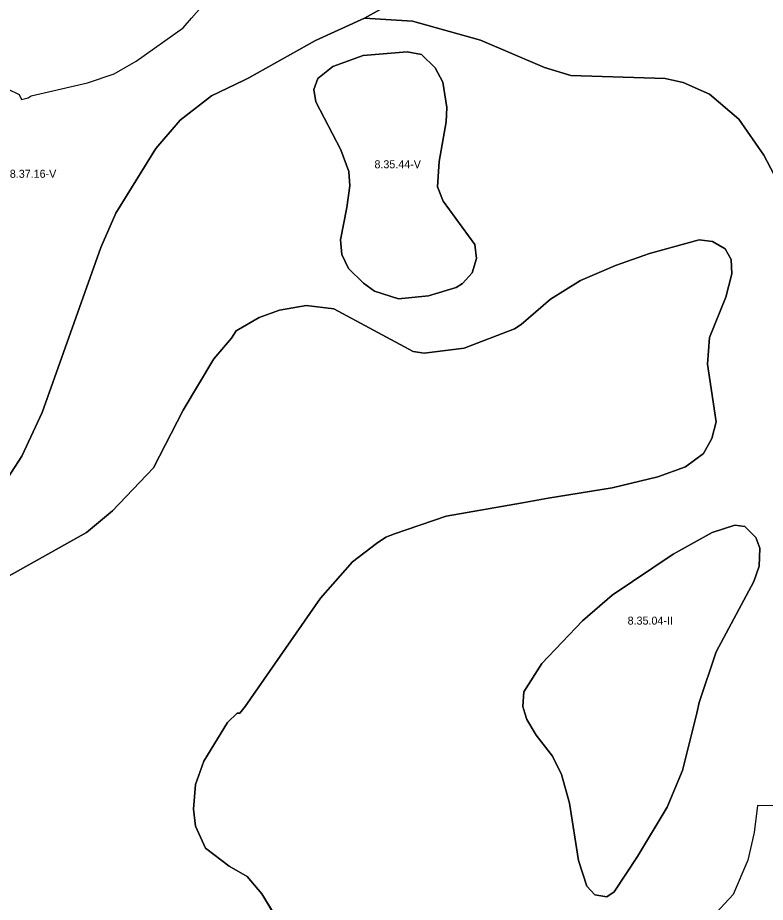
# Model space of a CAD drawing. Extents: x -547623 to -533936, y -1096714 to -1086523.
# Drawn here: x -542784 to -541850, y -1093236 to -1092131 of the extents above; entities that cross this region are included whole.
import ezdxf

# ---------------------------------------------------------------- set-up
doc = ezdxf.new("R2010")
doc.units = 0
for name, color, linetype in [('Vrstva 27', 7, 'Continuous'), ('Vrstva 28', 7, 'Continuous'), ('Vrstva 29', 7, 'Continuous')]:
    doc.layers.add(name, color=color, linetype=linetype)

msp = doc.modelspace()

# ---------------------------------------------------------------- linework, layer by layer
at = {"layer": 'Vrstva 28'}
for p, q in [((-542351, -1092132), (-542270.5, -1092087.5)), ((-542270.5, -1092087.5), (-542351, -1092132)), ((-542412, -1092160), (-542351, -1092132)), ((-542351, -1092132), (-542412, -1092160)), ((-542291, -1092136), (-542351, -1092132)), ((-542351, -1092132), (-542291, -1092136)), ((-542206, -1092159.5), (-542291, -1092136)), ((-542291, -1092136), (-542206, -1092159.5)), ((-542495.5, -1092206.5), (-542412, -1092160)), ((-542412, -1092160), (-542495.5, -1092206.5)), ((-542126, -1092193.5), (-542206, -1092159.5)), ((-542206, -1092159.5), (-542126, -1092193.5)), ((-542297.5, -1092174), (-542352.5, -1092178.5)), ((-542352.5, -1092178.5), (-542297.5, -1092174)), ((-542279.5, -1092177.5), (-542297.5, -1092174)), ((-542297.5, -1092174), (-542279.5, -1092177.5)), ((-542352.5, -1092178.5), (-542390.5, -1092192.5)), ((-542390.5, -1092192.5), (-542352.5, -1092178.5)), ((-542262.5, -1092194), (-542279.5, -1092177.5)), ((-542279.5, -1092177.5), (-542262.5, -1092194)), ((-542390.5, -1092192.5), (-542409, -1092207.5)), ((-542409, -1092207.5), (-542390.5, -1092192.5)), ((-542253, -1092212), (-542262.5, -1092194)), ((-542262.5, -1092194), (-542253, -1092212)), ((-542093, -1092203.5), (-542126, -1092193.5)), ((-542126, -1092193.5), (-542093, -1092203.5)), ((-542502, -1092210), (-542495.5, -1092206.5)), ((-542495.5, -1092206.5), (-542502, -1092210)), ((-542409, -1092207.5), (-542414, -1092221)), ((-542414, -1092221), (-542409, -1092207.5)), ((-541975.5, -1092207.5), (-542093, -1092203.5)), ((-542093, -1092203.5), (-541975.5, -1092207.5)), ((-541953, -1092212.5), (-541975.5, -1092207.5)), ((-541975.5, -1092207.5), (-541953, -1092212.5)), ((-542542, -1092229), (-542502, -1092210)), ((-542502, -1092210), (-542542, -1092229)), ((-542248, -1092243.5), (-542253, -1092212)), ((-542253, -1092212), (-542248, -1092243.5)), ((-541920, -1092227), (-541953, -1092212.5)), ((-541953, -1092212.5), (-541920, -1092227)), ((-542581, -1092259.5), (-542542, -1092229)), ((-542542, -1092229), (-542581, -1092259.5)), ((-542414, -1092221), (-542411.5, -1092236.5)), ((-542411.5, -1092236.5), (-542414, -1092221)), ((-541883.5, -1092258), (-541920, -1092227)), ((-541920, -1092227), (-541883.5, -1092258)), ((-542411.5, -1092236.5), (-542380.5, -1092296.5)), ((-542380.5, -1092296.5), (-542411.5, -1092236.5)), ((-542249, -1092261.5), (-542248, -1092243.5)), ((-542248, -1092243.5), (-542249, -1092261.5)), ((-542611.5, -1092295), (-542581, -1092259.5)), ((-542581, -1092259.5), (-542611.5, -1092295)), ((-542257.5, -1092311), (-542249, -1092261.5)), ((-542249, -1092261.5), (-542257.5, -1092311)), ((-541852, -1092303), (-541883.5, -1092258)), ((-541883.5, -1092258), (-541852, -1092303)), ((-542661.5, -1092375.5), (-542611.5, -1092295)), ((-542611.5, -1092295), (-542661.5, -1092375.5)), ((-542380.5, -1092296.5), (-542370.5, -1092323.5)), ((-542370.5, -1092323.5), (-542380.5, -1092296.5)), ((-541830.5, -1092344.5), (-541852, -1092303)), ((-541852, -1092303), (-541830.5, -1092344.5)), ((-542259.5, -1092342.5), (-542257.5, -1092311)), ((-542257.5, -1092311), (-542259.5, -1092342.5)), ((-542370.5, -1092323.5), (-542369, -1092341.5)), ((-542369, -1092341.5), (-542370.5, -1092323.5)), ((-542369, -1092341.5), (-542373, -1092368.5)), ((-542373, -1092368.5), (-542369, -1092341.5)), ((-542252.5, -1092360.5), (-542259.5, -1092342.5)), ((-542259.5, -1092342.5), (-542252.5, -1092360.5)), ((-542213, -1092414.5), (-542252.5, -1092360.5)), ((-542252.5, -1092360.5), (-542213, -1092414.5)), ((-542373, -1092368.5), (-542381, -1092409)), ((-542381, -1092409), (-542373, -1092368.5)), ((-542680, -1092418.5), (-542661.5, -1092375.5)), ((-542661.5, -1092375.5), (-542680, -1092418.5)), ((-542381, -1092409), (-542379, -1092427)), ((-542379, -1092427), (-542381, -1092409)), ((-542211, -1092432), (-542213, -1092414.5)), ((-542213, -1092414.5), (-542211, -1092432)), ((-541995, -1092426), (-541933, -1092409)), ((-541933, -1092409), (-541995, -1092426)), ((-541933, -1092409), (-541916, -1092411)), ((-541916, -1092411), (-541933, -1092409)), ((-541916, -1092411), (-541900.5, -1092420)), ((-541900.5, -1092420), (-541916, -1092411)), ((-542753.5, -1092624.5), (-542680, -1092418.5)), ((-542680, -1092418.5), (-542753.5, -1092624.5)), ((-542379, -1092427), (-542371, -1092444.5)), ((-542371, -1092444.5), (-542379, -1092427)), ((-542037.5, -1092441), (-541995, -1092426)), ((-541995, -1092426), (-542037.5, -1092441)), ((-541900.5, -1092420), (-541893, -1092433.5)), ((-541893, -1092433.5), (-541900.5, -1092420)), ((-542216.5, -1092450), (-542211, -1092432)), ((-542211, -1092432), (-542216.5, -1092450)), ((-541893, -1092433.5), (-541892, -1092451.5)), ((-541892, -1092451.5), (-541893, -1092433.5)), ((-542371, -1092444.5), (-542352, -1092463)), ((-542352, -1092463), (-542371, -1092444.5)), ((-542228.5, -1092463.5), (-542216.5, -1092450)), ((-542216.5, -1092450), (-542228.5, -1092463.5)), ((-542081, -1092459.5), (-542037.5, -1092441)), ((-542037.5, -1092441), (-542081, -1092459.5)), ((-542118.5, -1092483), (-542081, -1092459.5)), ((-542081, -1092459.5), (-542118.5, -1092483)), ((-541892, -1092451.5), (-541899.5, -1092480.5)), ((-541899.5, -1092480.5), (-541892, -1092451.5)), ((-542352, -1092463), (-542338.5, -1092473)), ((-542338.5, -1092473), (-542352, -1092463)), ((-542338.5, -1092473), (-542308.5, -1092482.5)), ((-542308.5, -1092482.5), (-542338.5, -1092473)), ((-542271, -1092479), (-542236.5, -1092468.5)), ((-542236.5, -1092468.5), (-542271, -1092479)), ((-542236.5, -1092468.5), (-542228.5, -1092463.5)), ((-542228.5, -1092463.5), (-542236.5, -1092468.5)), ((-542308.5, -1092482.5), (-542271, -1092479)), ((-542271, -1092479), (-542308.5, -1092482.5)), ((-542155, -1092514.5), (-542118.5, -1092483)), ((-542118.5, -1092483), (-542155, -1092514.5)), ((-541899.5, -1092480.5), (-541920, -1092531)), ((-541920, -1092531), (-541899.5, -1092480.5)), ((-542457, -1092496.5), (-542423.5, -1092491)), ((-542423.5, -1092491), (-542457, -1092496.5)), ((-542423.5, -1092491), (-542389, -1092495)), ((-542389, -1092495), (-542423.5, -1092491)), ((-542389, -1092495), (-542290, -1092548.5)), ((-542290, -1092548.5), (-542389, -1092495)), ((-542511, -1092522.5), (-542482.5, -1092506)), ((-542482.5, -1092506), (-542511, -1092522.5)), ((-542482.5, -1092506), (-542457, -1092496.5)), ((-542457, -1092496.5), (-542482.5, -1092506)), ((-542163.5, -1092520), (-542155, -1092514.5)), ((-542155, -1092514.5), (-542163.5, -1092520)), ((-542517, -1092531.5), (-542511, -1092522.5)), ((-542511, -1092522.5), (-542517, -1092531.5)), ((-542226.5, -1092544), (-542163.5, -1092520)), ((-542163.5, -1092520), (-542226.5, -1092544)), ((-542539, -1092557.5), (-542517, -1092531.5)), ((-542517, -1092531.5), (-542539, -1092557.5)), ((-541920, -1092531), (-541922.5, -1092564)), ((-541922.5, -1092564), (-541920, -1092531)), ((-542290, -1092548.5), (-542276.5, -1092550.5)), ((-542276.5, -1092550.5), (-542290, -1092548.5)), ((-542276.5, -1092550.5), (-542226.5, -1092544)), ((-542226.5, -1092544), (-542276.5, -1092550.5)), ((-542577.5, -1092621.5), (-542539, -1092557.5)), ((-542539, -1092557.5), (-542577.5, -1092621.5)), ((-541922.5, -1092564), (-541911.5, -1092636)), ((-541911.5, -1092636), (-541922.5, -1092564)), ((-542779, -1092679), (-542753.5, -1092624.5)), ((-542753.5, -1092624.5), (-542779, -1092679)), ((-542614.5, -1092693.5), (-542577.5, -1092621.5)), ((-542577.5, -1092621.5), (-542614.5, -1092693.5)), ((-541911.5, -1092636), (-541917, -1092657)), ((-541917, -1092657), (-541911.5, -1092636)), ((-541917, -1092657), (-541927.5, -1092675.5)), ((-541927.5, -1092675.5), (-541917, -1092657)), ((-542804.5, -1092719), (-542779, -1092679)), ((-542779, -1092679), (-542804.5, -1092719)), ((-541927.5, -1092675.5), (-541950, -1092692.5)), ((-541950, -1092692.5), (-541927.5, -1092675.5)), ((-542665.5, -1092747.5), (-542614.5, -1092693.5)), ((-542614.5, -1092693.5), (-542665.5, -1092747.5)), ((-541950, -1092692.5), (-541984.5, -1092705)), ((-541984.5, -1092705), (-541950, -1092692.5)), ((-541984.5, -1092705), (-542041.5, -1092718.5)), ((-542041.5, -1092718.5), (-541984.5, -1092705)), ((-542041.5, -1092718.5), (-542121.5, -1092731.5)), ((-542121.5, -1092731.5), (-542041.5, -1092718.5)), ((-542153.5, -1092737.5), (-542249, -1092754)), ((-542249, -1092754), (-542153.5, -1092737.5)), ((-542121.5, -1092731.5), (-542153.5, -1092737.5)), ((-542153.5, -1092737.5), (-542121.5, -1092731.5)), ((-542698, -1092774.5), (-542665.5, -1092747.5)), ((-542665.5, -1092747.5), (-542698, -1092774.5)), ((-542249, -1092754), (-542313.5, -1092776)), ((-542313.5, -1092776), (-542249, -1092754)), ((-541916.5, -1092774.5), (-541888.5, -1092765)), ((-541888.5, -1092765), (-541916.5, -1092774.5)), ((-541888.5, -1092765), (-541876, -1092767)), ((-541876, -1092767), (-541888.5, -1092765)), ((-541876, -1092767), (-541862, -1092780.5)), ((-541862, -1092780.5), (-541876, -1092767)), ((-542808.5, -1092836), (-542698, -1092774.5)), ((-542698, -1092774.5), (-542808.5, -1092836)), ((-542324, -1092780), (-542336, -1092788)), ((-542336, -1092788), (-542324, -1092780)), ((-542313.5, -1092776), (-542324, -1092780)), ((-542324, -1092780), (-542313.5, -1092776)), ((-541965.5, -1092801.5), (-541916.5, -1092774.5)), ((-541916.5, -1092774.5), (-541965.5, -1092801.5)), ((-541862, -1092780.5), (-541857, -1092794)), ((-541857, -1092794), (-541862, -1092780.5)), ((-542336, -1092788), (-542366, -1092811)), ((-542366, -1092811), (-542336, -1092788)), ((-542041.5, -1092852.5), (-541965.5, -1092801.5)), ((-541965.5, -1092801.5), (-542041.5, -1092852.5)), ((-541857, -1092794), (-541858, -1092816.5)), ((-541858, -1092816.5), (-541857, -1092794)), ((-542366, -1092811), (-542406, -1092856.5)), ((-542406, -1092856.5), (-542366, -1092811)), ((-541858, -1092816.5), (-541864.5, -1092835.5)), ((-541864.5, -1092835.5), (-541858, -1092816.5)), ((-541864.5, -1092835.5), (-541911.5, -1092923.5)), ((-541911.5, -1092923.5), (-541864.5, -1092835.5)), ((-542406, -1092856.5), (-542500, -1092991.5)), ((-542500, -1092991.5), (-542406, -1092856.5)), ((-542078.5, -1092884.5), (-542041.5, -1092852.5)), ((-542041.5, -1092852.5), (-542078.5, -1092884.5)), ((-542129.5, -1092938), (-542078.5, -1092884.5)), ((-542078.5, -1092884.5), (-542129.5, -1092938)), ((-541911.5, -1092923.5), (-541933, -1092986.5)), ((-541933, -1092986.5), (-541911.5, -1092923.5)), ((-542152, -1092973.5), (-542129.5, -1092938)), ((-542129.5, -1092938), (-542152, -1092973.5)), ((-542153, -1092991.5), (-542152, -1092973.5)), ((-542152, -1092973.5), (-542153, -1092991.5)), ((-542500, -1092991.5), (-542506.5, -1093000)), ((-542506.5, -1093000), (-542500, -1092991.5)), ((-542150.4, -1093000), (-542153, -1092991.5)), ((-542153, -1092991.5), (-542150.4, -1093000)), ((-541933, -1092986.5), (-541935.8, -1093000)), ((-541935.8, -1093000), (-541933, -1092986.5)), ((-542509.7, -1093000), (-542522, -1093011.5)), ((-542522, -1093011.5), (-542509.7, -1093000)), ((-542506.5, -1093000), (-542509.7, -1093000)), ((-542509.7, -1093000), (-542506.5, -1093000)), ((-542148, -1093008), (-542150.4, -1093000)), ((-542150.4, -1093000), (-542148, -1093008)), ((-541935.8, -1093000), (-541953.5, -1093071.5)), ((-541953.5, -1093071.5), (-541935.8, -1093000)), ((-542522, -1093011.5), (-542551.5, -1093060)), ((-542551.5, -1093060), (-542522, -1093011.5)), ((-542136.5, -1093027.5), (-542148, -1093008)), ((-542148, -1093008), (-542136.5, -1093027.5)), ((-542116, -1093053.5), (-542136.5, -1093027.5)), ((-542136.5, -1093027.5), (-542116, -1093053.5)), ((-542105, -1093076.5), (-542116, -1093053.5)), ((-542116, -1093053.5), (-542105, -1093076.5)), ((-542551.5, -1093060), (-542562, -1093089)), ((-542562, -1093089), (-542551.5, -1093060)), ((-542095, -1093112.5), (-542105, -1093076.5)), ((-542105, -1093076.5), (-542095, -1093112.5)), ((-541953.5, -1093071.5), (-541973, -1093117.5)), ((-541973, -1093117.5), (-541953.5, -1093071.5)), ((-542562, -1093089), (-542564.5, -1093120)), ((-542564.5, -1093120), (-542562, -1093089)), ((-542083.5, -1093184), (-542095, -1093112.5)), ((-542095, -1093112.5), (-542083.5, -1093184)), ((-542564.5, -1093120), (-542562, -1093141)), ((-542562, -1093141), (-542564.5, -1093120)), ((-541973, -1093117.5), (-542010, -1093179)), ((-542010, -1093179), (-541973, -1093117.5)), ((-542562, -1093141), (-542549.5, -1093168.5)), ((-542549.5, -1093168.5), (-542562, -1093141)), ((-542549.5, -1093168.5), (-542520, -1093191)), ((-542520, -1093191), (-542549.5, -1093168.5)), ((-542010, -1093179), (-542039, -1093223)), ((-542039, -1093223), (-542010, -1093179)), ((-542520, -1093191), (-542497.5, -1093204)), ((-542497.5, -1093204), (-542520, -1093191)), ((-542073, -1093216), (-542083.5, -1093184)), ((-542083.5, -1093184), (-542073, -1093216)), ((-542497.5, -1093204), (-542479, -1093225.5)), ((-542479, -1093225.5), (-542497.5, -1093204)), ((-542063, -1093227), (-542073, -1093216)), ((-542073, -1093216), (-542063, -1093227)), ((-542039, -1093223), (-542048, -1093229.5)), ((-542048, -1093229.5), (-542039, -1093223)), ((-542479, -1093225.5), (-542455.5, -1093264.5)), ((-542455.5, -1093264.5), (-542479, -1093225.5)), ((-542048, -1093229.5), (-542063, -1093227)), ((-542063, -1093227), (-542048, -1093229.5))]:
    msp.add_line(p, q, dxfattribs=at)
for points in [[(-542270.5, -1092087.5), (-542351, -1092132), (-542291, -1092136), (-542206, -1092159.5), (-542126, -1092193.5), (-542093, -1092203.5), (-541975.5, -1092207.5), (-541953, -1092212.5), (-541920, -1092227), (-541883.5, -1092258), (-541852, -1092303), (-541830.5, -1092344.5)], [(-542796.1, -1092220.6), (-542782, -1092227.4), (-542779.4, -1092233.6), (-542771.1, -1092231.6), (-542767.2, -1092228.9), (-542696.8, -1092213), (-542663.3, -1092201.6), (-542636.1, -1092185.7), (-542577.5, -1092144.2), (-542567, -1092132.1), (-542538.7, -1092099.6)], [(-541830.5, -1092344.5), (-541852, -1092303), (-541883.5, -1092258), (-541920, -1092227), (-541953, -1092212.5), (-541975.5, -1092207.5), (-542093, -1092203.5), (-542126, -1092193.5), (-542206, -1092159.5), (-542291, -1092136), (-542351, -1092132), (-542412, -1092160), (-542495.5, -1092206.5), (-542502, -1092210), (-542542, -1092229), (-542581, -1092259.5), (-542611.5, -1092295), (-542661.5, -1092375.5), (-542680, -1092418.5), (-542753.5, -1092624.5), (-542779, -1092679), (-542804.5, -1092719)], [(-542271, -1092479), (-542308.5, -1092482.5), (-542338.5, -1092473), (-542352, -1092463), (-542371, -1092444.5), (-542379, -1092427), (-542381, -1092409), (-542373, -1092368.5), (-542369, -1092341.5), (-542370.5, -1092323.5), (-542380.5, -1092296.5), (-542411.5, -1092236.5), (-542414, -1092221), (-542409, -1092207.5), (-542390.5, -1092192.5), (-542352.5, -1092178.5), (-542297.5, -1092174), (-542279.5, -1092177.5), (-542262.5, -1092194), (-542253, -1092212), (-542248, -1092243.5), (-542249, -1092261.5), (-542257.5, -1092311), (-542259.5, -1092342.5), (-542252.5, -1092360.5), (-542213, -1092414.5), (-542211, -1092432), (-542216.5, -1092450), (-542228.5, -1092463.5), (-542236.5, -1092468.5), (-542271, -1092479)], [(-542297.5, -1092174), (-542352.5, -1092178.5), (-542390.5, -1092192.5), (-542409, -1092207.5), (-542414, -1092221), (-542411.5, -1092236.5), (-542380.5, -1092296.5), (-542370.5, -1092323.5), (-542369, -1092341.5), (-542373, -1092368.5), (-542381, -1092409), (-542379, -1092427), (-542371, -1092444.5), (-542352, -1092463), (-542338.5, -1092473), (-542308.5, -1092482.5), (-542271, -1092479), (-542236.5, -1092468.5), (-542228.5, -1092463.5), (-542216.5, -1092450), (-542211, -1092432), (-542213, -1092414.5), (-542252.5, -1092360.5), (-542259.5, -1092342.5), (-542257.5, -1092311), (-542249, -1092261.5), (-542248, -1092243.5), (-542253, -1092212), (-542262.5, -1092194), (-542279.5, -1092177.5), (-542297.5, -1092174)], [(-542808.5, -1092836), (-542698, -1092774.5), (-542665.5, -1092747.5), (-542614.5, -1092693.5), (-542577.5, -1092621.5), (-542539, -1092557.5), (-542517, -1092531.5), (-542511, -1092522.5), (-542482.5, -1092506), (-542457, -1092496.5), (-542423.5, -1092491), (-542389, -1092495), (-542290, -1092548.5), (-542276.5, -1092550.5), (-542226.5, -1092544), (-542163.5, -1092520), (-542155, -1092514.5), (-542118.5, -1092483), (-542081, -1092459.5), (-542037.5, -1092441), (-541995, -1092426), (-541933, -1092409), (-541916, -1092411), (-541900.5, -1092420), (-541893, -1092433.5), (-541892, -1092451.5), (-541899.5, -1092480.5), (-541920, -1092531), (-541922.5, -1092564), (-541911.5, -1092636), (-541917, -1092657), (-541927.5, -1092675.5), (-541950, -1092692.5), (-541984.5, -1092705), (-542041.5, -1092718.5), (-542121.5, -1092731.5), (-542153.5, -1092737.5), (-542249, -1092754), (-542313.5, -1092776), (-542324, -1092780), (-542336, -1092788), (-542366, -1092811), (-542406, -1092856.5), (-542500, -1092991.5), (-542506.5, -1093000), (-542509.7, -1093000), (-542522, -1093011.5), (-542551.5, -1093060), (-542562, -1093089), (-542564.5, -1093120), (-542562, -1093141), (-542549.5, -1093168.5), (-542520, -1093191), (-542497.5, -1093204), (-542479, -1093225.5), (-542455.5, -1093264.5)], [(-542136.5, -1093027.5), (-542116, -1093053.5), (-542105, -1093076.5), (-542095, -1093112.5), (-542083.5, -1093184), (-542073, -1093216), (-542063, -1093227), (-542048, -1093229.5), (-542039, -1093223), (-542010, -1093179), (-541973, -1093117.5), (-541953.5, -1093071.5), (-541935.8, -1093000), (-541933, -1092986.5), (-541911.5, -1092923.5), (-541864.5, -1092835.5), (-541858, -1092816.5), (-541857, -1092794), (-541862, -1092780.5), (-541876, -1092767), (-541888.5, -1092765), (-541916.5, -1092774.5), (-541965.5, -1092801.5), (-542041.5, -1092852.5), (-542078.5, -1092884.5), (-542129.5, -1092938), (-542152, -1092973.5), (-542153, -1092991.5), (-542150.4, -1093000), (-542148, -1093008), (-542136.5, -1093027.5)], [(-542039, -1093223), (-542048, -1093229.5), (-542063, -1093227), (-542073, -1093216), (-542083.5, -1093184), (-542095, -1093112.5), (-542105, -1093076.5), (-542116, -1093053.5), (-542136.5, -1093027.5), (-542148, -1093008), (-542150.4, -1093000), (-542153, -1092991.5), (-542152, -1092973.5), (-542129.5, -1092938), (-542078.5, -1092884.5), (-542041.5, -1092852.5), (-541965.5, -1092801.5), (-541916.5, -1092774.5), (-541888.5, -1092765), (-541876, -1092767), (-541862, -1092780.5), (-541857, -1092794), (-541858, -1092816.5), (-541864.5, -1092835.5), (-541911.5, -1092923.5), (-541933, -1092986.5), (-541935.8, -1093000), (-541953.5, -1093071.5), (-541973, -1093117.5), (-542010, -1093179), (-542039, -1093223)]]:
    msp.add_lwpolyline(points, dxfattribs=at)
at = {"layer": 'Vrstva 29'}
msp.add_lwpolyline([(-541540.3, -1093131.5), (-541579.6, -1093092.6), (-541637.9, -1093082.7), (-541672, -1093081), (-541677.8, -1093113.2), (-541673.1, -1093146.7), (-541707.9, -1093194.2), (-541742.5, -1093154.3), (-541766.3, -1093114.3), (-541810.5, -1093115.9), (-541860.1, -1093115.3), (-541864.2, -1093149), (-541872.1, -1093183.4), (-541890.4, -1093226.3), (-541916.5, -1093254.9)], dxfattribs=at)

# ---------------------------------------------------------------- texts
at = {"layer": 'Vrstva 27'}
for s, p in [('8.35.44-V', (-542338.4, -1092319.5)), ('8.37.16-V', (-542793.8, -1092331.4)), ('8.35.04-II', (-542022.2, -1092889.4))]:
    msp.add_text(s, height=10, dxfattribs=at).set_placement(p)

doc.saveas('drawing.dxf')
